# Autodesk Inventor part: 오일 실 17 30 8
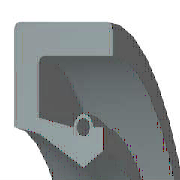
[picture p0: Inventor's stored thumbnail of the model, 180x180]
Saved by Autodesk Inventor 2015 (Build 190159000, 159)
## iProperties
Created: 2012-02
Part Number: 오일 실 17 30 8
Material: 고무
Description: 오일-실
Document SubType Name: Modeling
Standard: KS B 2804
Designer: mduedu
Standards Organization: KS
Language: ko-KR
Size Designation: S - 17 30 8
Categories: <MemberInstance><Categories><Category DisplayName="샤프트 부품" InternalName="7f7aeb1f-a693-4053-b835-cee3144e0d98" Mnemonic="SHFT"><Category DisplayName="실링" Intern
Density: 0.93 g/cm^3
Appearance: 고무 - 검은색 - 버전 1.1
IsCustomPart: 1
Author: mduedu
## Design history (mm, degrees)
revolve "본체" stored, may be unused: angle "d17" = 90 deg
revolve "스프링1" stored, may be unused: angle "d18" = 90 deg
body "Solid1"
sketch "스케치1"
  geometry: L1 (0, 15)-(8, 15); L2 (8, 15)-(8, 13.75); L3 (8, 13.75)-(1.75, 13.75); L4 (0, 15)-(0, 10.6); L5 (0, 10.6)-(1.75, 10.25); L6 (1.75, 10.25)-(4.9, 8.5); L7 (4.9, 8.5)-(0, 8.5); L8 (6.3, 9.375)-(6.3, 10.6); L9 (0, 0)-(9.586, 0) reference; L10 (4.9, 8.5)-(6.3, 9.375); L11 (0, 18)-(0, -3) reference; L12 (-1.917, 0)-(11.503, 0) reference; L13 (4.2, 10.6)-(1.75, 11.09); L14 (1.75, 11.09)-(1.75, 13.75); L15 (6.3, 10.6)-(5.6, 10.6); C1 r 0.455 at (4.9, 10.6); A1 r 0.7 centre (4.9, 10.6) between (5.6, 10.6) and (4.2, 10.6)
  constraints: 26 end point, 5 horizontal alignment, 4 perpendicular, 2 centre point, 2 collinear, 2 horizontal, 2 parallel, 2 point on circle, 2 point on line, 2 vertical alignment, 1 coincident
  dimensions: "d0" = 30 diameter of L1 L9 (= SD2); "d1" = 18.75 diameter of L8.start L9 (= ABDM); "d2" = 1.25 distance of L1.end L2.end (computed from SD); "d3" = 0.91 diameter of C1 (= SPDI); "d4" = 1.4 diameter of A1 (= SPDA); "d5" = 17 diameter of L6.end L9 (= NND); "d6" = 20.5 diameter of L5.end L9 (= TKDM); "d7" = 21.2 diameter of L4.end L9 (= HLDM); "d8" = 4.9 distance from line of C1.centre L4 (= SPDST); "d9" = 6.3 distance between parallel lines of L8 L4 (= SDI); "d10" = 8 distance between parallel lines of L2 L4 (= SWDT); "d12" = 1.75 distance between parallel lines of L14 L4 (= SD)
fillet "모깎기1" dims "d11" = 0.3 (= RR)
other parameters: "SD2" = 30 [user parameter; used in 1 equation term], "SWDT" = 8 [user parameter; used in 1 equation term], "RR" = 0.3 [user parameter; used in 1 equation term], "SD" = 1.75 [user parameter; used in 2 equation terms], "NND" = 17 [user parameter; used in 1 equation term], "SPDA" = 1.4 [user parameter; used in 1 equation term], "SPDI" = 0.91 [user parameter; used in 1 equation term], "TKDM" = 20.5 [user parameter; used in 1 equation term], "HLDM" = 21.2 [user parameter; used in 1 equation term], "ABDM" = 18.75 [user parameter; used in 1 equation term], "SDI" = 6.3 [user parameter; used in 1 equation term], "SPDST" = 4.9 [user parameter; used in 1 equation term], "d13" = 0, "d14" = 0, "d15" = 0, "LAB" = 0.35 [user parameter]
